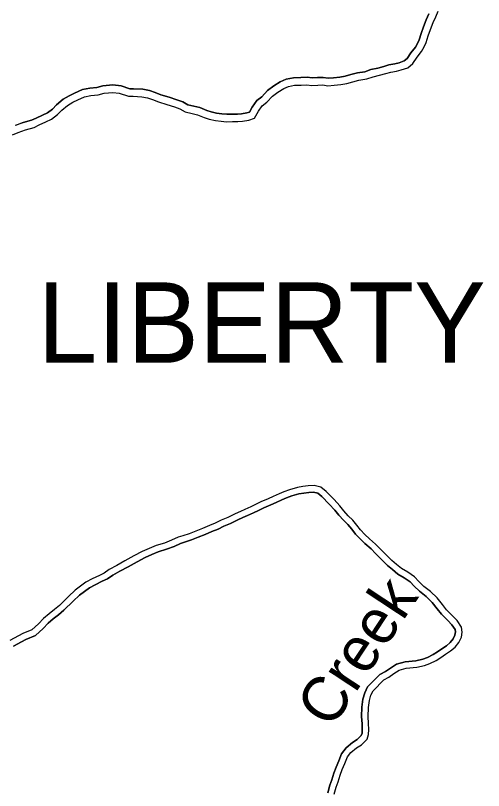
# Model space of a CAD drawing. Extents: x -12.1 to 34, y 0 to 22.
# Drawn here: x -6.611 to -5.682, y 15.867 to 17.405 of the extents above; entities that cross this region are included whole.
import ezdxf

# ---------------------------------------------------------------- set-up
doc = ezdxf.new("R2010")
doc.units = 0
for name, color, linetype in [('GM_X_Major_River', 7, 'Continuous'), ('GM_X_Major_River_Text', 7, 'Continuous'), ('GM_X_Township_Text', 7, 'Continuous')]:
    doc.layers.add(name, color=color, linetype=linetype)

msp = doc.modelspace()

# ---------------------------------------------------------------- linework, layer by layer
at = {"layer": 'GM_X_Major_River'}
for points in [[(-6.6058, 17.1728), (-6.5913, 17.1779), (-6.5739, 17.1827), (-6.5637, 17.1874), (-6.5506, 17.1935), (-6.5396, 17.1989), (-6.5273, 17.2079), (-6.5192, 17.2169), (-6.5079, 17.2262), (-6.4973, 17.2324), (-6.4874, 17.2374), (-6.4736, 17.2436), (-6.4612, 17.2458), (-6.447, 17.2473), (-6.4349, 17.2503), (-6.4179, 17.2522), (-6.4048, 17.2505), (-6.3866, 17.2443), (-6.377, 17.2443), (-6.36, 17.2434), (-6.349, 17.2414), (-6.339, 17.2379), (-6.3272, 17.2334), (-6.3105, 17.2282), (-6.2952, 17.2233), (-6.2849, 17.2195), (-6.2738, 17.2135), (-6.2603, 17.2104), (-6.2493, 17.2077), (-6.2365, 17.2024), (-6.2265, 17.199), (-6.214, 17.1962), (-6.2027, 17.1949), (-6.1917, 17.1939), (-6.1799, 17.194), (-6.1693, 17.1941), (-6.1601, 17.1949), (-6.1477, 17.1968), (-6.136, 17.2011), (-6.1283, 17.2151), (-6.1209, 17.2254), (-6.1117, 17.2326), (-6.1008, 17.2448), (-6.0899, 17.2527), (-6.0782, 17.2596), (-6.0687, 17.2639), (-6.057, 17.2662), (-6.0438, 17.2666), (-6.0321, 17.2671), (-6.0225, 17.2661), (-6.0108, 17.2665), (-6.0009, 17.267), (-5.9909, 17.2653), (-5.9778, 17.2665), (-5.965, 17.2676), (-5.953, 17.2695), (-5.9413, 17.2732), (-5.9289, 17.2761), (-5.9133, 17.2787), (-5.9009, 17.2831), (-5.8878, 17.2861), (-5.8754, 17.2894), (-5.8658, 17.292), (-5.8541, 17.2942), (-5.8449, 17.2968), (-5.8315, 17.3011), (-5.8216, 17.3094), (-5.8135, 17.3219), (-5.8044, 17.3334), (-5.7995, 17.3423), (-5.7953, 17.3512), (-5.7915, 17.3641), (-5.7866, 17.3769), (-5.7814, 17.3908), (-5.7765, 17.4023), (-5.7717, 17.4133)], [(-5.7902, 17.4082), (-5.7952, 17.3964), (-5.8006, 17.3822), (-5.8056, 17.3688), (-5.8093, 17.3565), (-5.8128, 17.349), (-5.8168, 17.3416), (-5.8256, 17.3306), (-5.8329, 17.3194), (-5.8388, 17.3144), (-5.8492, 17.311), (-5.8575, 17.3087), (-5.8692, 17.3065), (-5.8792, 17.3038), (-5.8913, 17.3005), (-5.905, 17.2974), (-5.917, 17.2932), (-5.9318, 17.2907), (-5.9452, 17.2875), (-5.9564, 17.2841), (-5.9669, 17.2824), (-5.9791, 17.2813), (-5.9903, 17.2803), (-5.9999, 17.2819), (-6.0114, 17.2814), (-6.0221, 17.281), (-6.0316, 17.282), (-6.0444, 17.2815), (-6.0586, 17.281), (-6.0732, 17.2782), (-6.0851, 17.2728), (-6.098, 17.2652), (-6.1108, 17.2559), (-6.1219, 17.2435), (-6.1318, 17.2358), (-6.1409, 17.223), (-6.1463, 17.2131), (-6.1514, 17.2112), (-6.1618, 17.2097), (-6.17, 17.209), (-6.1801, 17.2089), (-6.191, 17.2088), (-6.2011, 17.2097), (-6.2116, 17.2109), (-6.2224, 17.2133), (-6.2312, 17.2164), (-6.2446, 17.2218), (-6.2568, 17.2249), (-6.2685, 17.2276), (-6.2787, 17.2331), (-6.2904, 17.2374), (-6.306, 17.2424), (-6.3223, 17.2474), (-6.3339, 17.2519), (-6.3451, 17.2558), (-6.3582, 17.2582), (-6.3767, 17.2592), (-6.3842, 17.2592), (-6.4014, 17.2651), (-6.4178, 17.2672), (-6.4375, 17.265), (-6.4496, 17.262), (-6.4633, 17.2605), (-6.478, 17.2579), (-6.4938, 17.2508), (-6.5044, 17.2454), (-6.5164, 17.2385), (-6.5295, 17.2277), (-6.5373, 17.2191), (-6.5473, 17.2117), (-6.557, 17.2069), (-6.5699, 17.2009), (-6.579, 17.1967), (-6.5957, 17.1921), (-6.6112, 17.1867)], [(-6.6107, 17.1869), (-6.5957, 17.1921), (-6.579, 17.1967), (-6.5699, 17.2009), (-6.557, 17.2069), (-6.5473, 17.2117), (-6.5373, 17.2191), (-6.5295, 17.2277), (-6.5164, 17.2385), (-6.5044, 17.2454), (-6.4938, 17.2508), (-6.478, 17.2579), (-6.4633, 17.2605), (-6.4496, 17.262), (-6.4375, 17.265), (-6.4178, 17.2672), (-6.4014, 17.2651), (-6.3842, 17.2592), (-6.3767, 17.2592), (-6.3582, 17.2582), (-6.3451, 17.2558), (-6.3339, 17.2519), (-6.3223, 17.2474), (-6.306, 17.2424), (-6.2904, 17.2374), (-6.2787, 17.2331), (-6.2685, 17.2276), (-6.2568, 17.2249), (-6.2446, 17.2218), (-6.2312, 17.2164), (-6.2224, 17.2133), (-6.2116, 17.2109), (-6.2011, 17.2097), (-6.191, 17.2088), (-6.1801, 17.2089), (-6.17, 17.209), (-6.1618, 17.2097), (-6.1514, 17.2112), (-6.1463, 17.2131), (-6.1409, 17.223), (-6.1318, 17.2358), (-6.1219, 17.2435), (-6.1108, 17.2559), (-6.098, 17.2652), (-6.0851, 17.2728), (-6.0732, 17.2782), (-6.0586, 17.281), (-6.0444, 17.2815), (-6.0316, 17.282), (-6.0221, 17.281), (-6.0114, 17.2814), (-5.9999, 17.2819), (-5.9903, 17.2803), (-5.9791, 17.2813), (-5.9669, 17.2824), (-5.9564, 17.2841), (-5.9452, 17.2875), (-5.9318, 17.2907), (-5.917, 17.2932), (-5.905, 17.2974), (-5.8913, 17.3005), (-5.8792, 17.3038), (-5.8692, 17.3065), (-5.8575, 17.3087), (-5.8492, 17.311), (-5.8388, 17.3144), (-5.8329, 17.3194), (-5.8256, 17.3306), (-5.8168, 17.3416), (-5.8128, 17.349), (-5.8093, 17.3565), (-5.8056, 17.3688), (-5.8006, 17.3822), (-5.7952, 17.3964), (-5.7902, 17.4082)], [(-6.6168, 17.1681), (-6.6058, 17.1728)], [(-5.9782, 15.8594), (-5.9744, 15.8729), (-5.9702, 15.8836), (-5.966, 15.8968), (-5.9622, 15.9085), (-5.957, 15.9203), (-5.9517, 15.9331), (-5.9451, 15.942), (-5.9338, 15.951), (-5.9239, 15.9575), (-5.9127, 15.9686), (-5.9099, 15.9778), (-5.9092, 15.9878), (-5.9097, 15.9998), (-5.9105, 16.0137), (-5.9102, 16.0311), (-5.9082, 16.045), (-5.9051, 16.0557), (-5.9009, 16.0646), (-5.8794, 16.0861), (-5.8692, 16.0918), (-5.8593, 16.0986), (-5.8487, 16.1051), (-5.8349, 16.1091), (-5.8137, 16.1111), (-5.7985, 16.1148), (-5.7879, 16.1187), (-5.7752, 16.1249), (-5.766, 16.1306), (-5.7568, 16.1371), (-5.7473, 16.1436), (-5.7381, 16.1511), (-5.7308, 16.1604), (-5.7255, 16.1711), (-5.7242, 16.1811), (-5.7253, 16.191), (-5.7339, 16.2037), (-5.7428, 16.2132), (-5.7549, 16.2252), (-5.7632, 16.2355), (-5.7735, 16.2489), (-5.7871, 16.2612), (-5.7999, 16.2717), (-5.8099, 16.2813), (-5.8184, 16.2904), (-5.832, 16.2999), (-5.8441, 16.3069), (-5.854, 16.315), (-5.8637, 16.3228), (-5.8754, 16.3347), (-5.8865, 16.3464), (-5.8958, 16.3555), (-5.9082, 16.3661), (-5.9171, 16.3749), (-5.9257, 16.3841), (-5.9329, 16.3933), (-5.9411, 16.4031), (-5.95, 16.412), (-5.9589, 16.4218), (-5.9668, 16.4314), (-5.9782, 16.4441), (-5.9939, 16.4599), (-6.0046, 16.4687), (-6.0181, 16.4718), (-6.0297, 16.4714), (-6.0404, 16.4699), (-6.051, 16.468), (-6.0665, 16.4636), (-6.0779, 16.4593), (-6.087, 16.4553), (-6.099, 16.4499), (-6.1093, 16.4452), (-6.1234, 16.4394), (-6.134, 16.434)], [(-6.1282, 16.4223), (-6.118, 16.4275), (-6.1041, 16.4332), (-6.0936, 16.438), (-6.0818, 16.4434), (-6.0729, 16.4472), (-6.0624, 16.4512), (-6.0481, 16.4553), (-6.0383, 16.457), (-6.0286, 16.4583), (-6.0193, 16.4587), (-6.0105, 16.4567), (-6.0027, 16.4503), (-5.9877, 16.4351), (-5.9767, 16.4228), (-5.9688, 16.4133), (-5.9594, 16.4029), (-5.9507, 16.3943), (-5.943, 16.3851), (-5.9357, 16.3756), (-5.9265, 16.3658), (-5.9171, 16.3565), (-5.9046, 16.3459), (-5.8958, 16.3372), (-5.8848, 16.3257), (-5.8724, 16.3131), (-5.8622, 16.3049), (-5.8515, 16.2961), (-5.839, 16.2889), (-5.8271, 16.2805), (-5.8192, 16.2721), (-5.8086, 16.262), (-5.7956, 16.2513), (-5.7832, 16.24), (-5.7734, 16.2274), (-5.7647, 16.2165), (-5.7522, 16.2041), (-5.7441, 16.1955), (-5.7379, 16.1863), (-5.7373, 16.1812), (-5.7382, 16.1749), (-5.7419, 16.1674), (-5.7475, 16.1603), (-5.7551, 16.154), (-5.7643, 16.1478), (-5.7732, 16.1415), (-5.7815, 16.1363), (-5.793, 16.1308), (-5.8023, 16.1273), (-5.8158, 16.124), (-5.8374, 16.122), (-5.854, 16.1172), (-5.8664, 16.1096), (-5.8761, 16.1029), (-5.8874, 16.0965), (-5.9117, 16.0722), (-5.9173, 16.0603), (-5.921, 16.0478), (-5.9233, 16.0321), (-5.9235, 16.0134), (-5.9227, 15.9992), (-5.9223, 15.988), (-5.9228, 15.9801), (-5.9242, 15.9755), (-5.9322, 15.9677), (-5.9414, 15.9616), (-5.9545, 15.9512), (-5.9632, 15.9396), (-5.969, 15.9254), (-5.9744, 15.9132), (-5.9785, 15.9007), (-5.9825, 15.8879), (-5.9868, 15.877), (-5.991, 15.8618)], [(-5.991, 15.8618), (-5.9868, 15.877), (-5.9825, 15.8879), (-5.9785, 15.9007), (-5.9744, 15.9132), (-5.969, 15.9254), (-5.9632, 15.9396), (-5.9545, 15.9512), (-5.9414, 15.9616), (-5.9322, 15.9677), (-5.9242, 15.9755), (-5.9228, 15.9801), (-5.9223, 15.988), (-5.9227, 15.9992), (-5.9235, 16.0134), (-5.9233, 16.0321), (-5.921, 16.0478), (-5.9173, 16.0603), (-5.9117, 16.0722), (-5.8874, 16.0965), (-5.8761, 16.1029), (-5.8664, 16.1096), (-5.854, 16.1172), (-5.8374, 16.122), (-5.8158, 16.124), (-5.8023, 16.1273), (-5.793, 16.1308), (-5.7815, 16.1363), (-5.7732, 16.1415), (-5.7643, 16.1478), (-5.7551, 16.154), (-5.7475, 16.1603), (-5.7419, 16.1674), (-5.7382, 16.1749), (-5.7373, 16.1812), (-5.7379, 16.1863), (-5.7441, 16.1955), (-5.7522, 16.2041), (-5.7647, 16.2165), (-5.7734, 16.2274), (-5.7832, 16.24), (-5.7956, 16.2513), (-5.8086, 16.262), (-5.8192, 16.2721), (-5.8271, 16.2805), (-5.839, 16.2889), (-5.8515, 16.2961), (-5.8622, 16.3049), (-5.8724, 16.3131), (-5.8848, 16.3257), (-5.8958, 16.3372), (-5.9046, 16.3459), (-5.9171, 16.3565), (-5.9265, 16.3658), (-5.9357, 16.3756), (-5.943, 16.3851), (-5.9507, 16.3943), (-5.9594, 16.4029), (-5.9688, 16.4133), (-5.9767, 16.4228), (-5.9877, 16.4351), (-6.0027, 16.4503), (-6.0105, 16.4567), (-6.0193, 16.4587), (-6.0286, 16.4583), (-6.0383, 16.457), (-6.0481, 16.4553), (-6.0624, 16.4512), (-6.0729, 16.4472), (-6.0818, 16.4434), (-6.0936, 16.438), (-6.1041, 16.4332), (-6.118, 16.4275), (-6.1281, 16.4224)], [(-6.134, 16.434), (-6.1436, 16.4293), (-6.1552, 16.4242), (-6.1644, 16.4203), (-6.1746, 16.4159), (-6.1895, 16.4087), (-6.2025, 16.4033), (-6.2142, 16.3971), (-6.2259, 16.3924), (-6.2393, 16.3866), (-6.2527, 16.3812), (-6.2658, 16.3762), (-6.2789, 16.3718), (-6.2881, 16.3692), (-6.3011, 16.3631), (-6.3153, 16.3577), (-6.3319, 16.3526), (-6.3453, 16.3471), (-6.3591, 16.341), (-6.3757, 16.332), (-6.3937, 16.3223), (-6.4099, 16.3133), (-6.4248, 16.305), (-6.4346, 16.2982), (-6.4442, 16.2935), (-6.4586, 16.2866), (-6.471, 16.2798), (-6.4819, 16.2723), (-6.4922, 16.264), (-6.5055, 16.2518), (-6.5235, 16.2339), (-6.5337, 16.2257), (-6.5443, 16.2175), (-6.5552, 16.2078), (-6.565, 16.1974), (-6.5784, 16.1852), (-6.5961, 16.178), (-6.6053, 16.1733), (-6.6219, 16.164)], [(-6.1283, 16.4223), (-6.1381, 16.4174), (-6.15, 16.4122), (-6.1593, 16.4082), (-6.1692, 16.404), (-6.1841, 16.3968), (-6.197, 16.3914), (-6.2087, 16.3853), (-6.2208, 16.3804), (-6.2343, 16.3746), (-6.2479, 16.3691), (-6.2614, 16.3639), (-6.2751, 16.3593), (-6.2835, 16.3569), (-6.296, 16.3511), (-6.311, 16.3453), (-6.3275, 16.3403), (-6.3402, 16.3351), (-6.3533, 16.3293), (-6.3695, 16.3205), (-6.3874, 16.3108), (-6.4036, 16.3019), (-6.4178, 16.2939), (-6.428, 16.2869), (-6.4385, 16.2817), (-6.4527, 16.275), (-6.4641, 16.2687), (-6.4741, 16.2618), (-6.4837, 16.2541), (-6.4965, 16.2424), (-6.5148, 16.2242), (-6.5256, 16.2155), (-6.5359, 16.2074), (-6.5461, 16.1984), (-6.5559, 16.1881), (-6.5714, 16.174), (-6.5906, 16.1661), (-6.5991, 16.1618), (-6.6151, 16.1528)], [(-6.6151, 16.1528), (-6.5991, 16.1618), (-6.5906, 16.1661), (-6.5714, 16.174), (-6.5559, 16.1881), (-6.5461, 16.1984), (-6.5359, 16.2074), (-6.5256, 16.2155), (-6.5148, 16.2242), (-6.4965, 16.2424), (-6.4837, 16.2541), (-6.4741, 16.2618), (-6.4641, 16.2687), (-6.4527, 16.275), (-6.4385, 16.2817), (-6.428, 16.2869), (-6.4178, 16.2939), (-6.4036, 16.3019), (-6.3874, 16.3108), (-6.3695, 16.3205), (-6.3533, 16.3293), (-6.3402, 16.3351), (-6.3275, 16.3403), (-6.311, 16.3453), (-6.296, 16.3511), (-6.2835, 16.3569), (-6.2751, 16.3593), (-6.2614, 16.3639), (-6.2479, 16.3691), (-6.2343, 16.3746), (-6.2208, 16.3804), (-6.2087, 16.3853), (-6.197, 16.3914), (-6.1841, 16.3968), (-6.1692, 16.404), (-6.1593, 16.4082), (-6.15, 16.4122), (-6.1381, 16.4174), (-6.1282, 16.4223)]]:
    msp.add_lwpolyline(points, dxfattribs=at)

# ---------------------------------------------------------------- texts
at = {"layer": 'GM_X_Major_River_Text'}
msp.add_text('Creek', height=0.0888, rotation=56.5714, dxfattribs=at).set_placement((-5.9837, 15.9866))
at = {"layer": 'GM_X_Township_Text'}
msp.add_text('LIBERTY', height=0.1598, rotation=0, dxfattribs=at).set_placement((-6.5675, 16.7154))

doc.saveas('drawing.dxf')
